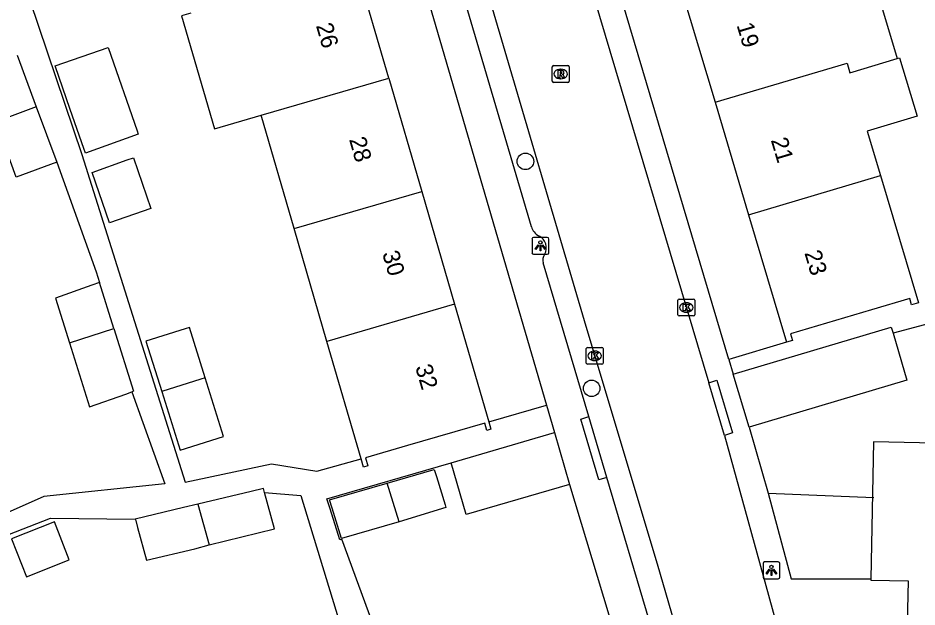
# Model space of a CAD drawing. Extents: x 162532 to 163264, y 381233 to 382042.
# Drawn here: x 162901.4 to 162954.6, y 381795 to 381829.9 of the extents above; entities that cross this region are included whole.
import ezdxf

# ---------------------------------------------------------------- set-up
doc = ezdxf.new("R2010")
doc.units = 0
for name, color, linetype in [('IMGEO_Boom', 7, 'Continuous'), ('IMGEO_Kolk', 7, 'Continuous'), ('IMGEO_Lichtpunt', 7, 'Continuous'), ('IMGEO_Muur', 7, 'Continuous'), ('IMGEO_Pand', 7, 'Continuous'), ('IMGEO_Pand_nummerreeks', 7, 'Continuous'), ('IMGEO_Rijbaan_lokaal_open', 7, 'Continuous'), ('IMGEO_Rioolput', 7, 'Continuous'), ('IMGEO_Voetpad_open', 7, 'Continuous')]:
    doc.layers.add(name, color=color, linetype=linetype)

msp = doc.modelspace()

# ---------------------------------------------------------------- linework, layer by layer
at = {"layer": 'IMGEO_Boom'}
for centre in [(162931.471, 381821.418), (162935.39, 381807.979)]:
    msp.add_circle(centre, 0.489, dxfattribs=at)
at = {"layer": 'IMGEO_Kolk'}
for p, q in [((162940.571, 381813.266), (162941.423, 381813.266)), ((162940.496, 381812.34), (162940.496, 381813.192)), ((162940.984, 381813.046), (162941.009, 381813.046)), ((162941.497, 381813.192), (162941.497, 381812.34)), ((162941.423, 381812.266), (162940.571, 381812.266)), ((162941.007, 381812.486), (162940.982, 381812.486)), ((162935.074, 381809.477), (162935.074, 381810.329)), ((162935.149, 381810.403), (162936.001, 381810.403)), ((162935.562, 381810.183), (162935.587, 381810.183)), ((162936.075, 381810.329), (162936.075, 381809.477)), ((162935.585, 381809.623), (162935.56, 381809.623)), ((162936.001, 381809.403), (162935.149, 381809.403))]:
    msp.add_line(p, q, dxfattribs=at)
for points in [[(162940.571, 381813.266), (162941.423, 381813.266)], [(162940.496, 381812.34), (162940.496, 381813.192)], [(162940.817, 381812.966), (162940.94, 381812.966), (162940.94, 381812.815), (162941.07, 381812.966), (162941.234, 381812.966), (162941.088, 381812.815), (162941.241, 381812.566), (162941.089, 381812.566), (162941.004, 381812.73), (162940.94, 381812.663), (162940.94, 381812.566), (162940.817, 381812.566), (162940.817, 381812.966)], [(162941.497, 381813.192), (162941.497, 381812.34)], [(162941.423, 381812.266), (162940.571, 381812.266)], [(162935.074, 381809.477), (162935.074, 381810.329)], [(162935.149, 381810.403), (162936.001, 381810.403)], [(162935.395, 381810.103), (162935.518, 381810.103), (162935.518, 381809.952), (162935.648, 381810.103), (162935.812, 381810.103), (162935.666, 381809.952), (162935.819, 381809.703), (162935.667, 381809.703), (162935.582, 381809.867), (162935.518, 381809.8), (162935.518, 381809.703), (162935.395, 381809.703), (162935.395, 381810.103)], [(162936.075, 381810.329), (162936.075, 381809.477)], [(162936.001, 381809.403), (162935.149, 381809.403)]]:
    msp.add_lwpolyline(points, dxfattribs=at)
for centre, start, end in [((162940.573, 381813.19), 91.552, 178.448), ((162940.573, 381813.19), 91.552, 178.448), ((162941.421, 381813.19), 1.552, 88.448), ((162941.421, 381813.19), 1.552, 88.448), ((162940.573, 381812.342), 181.552, 268.448), ((162940.573, 381812.342), 181.552, 268.448), ((162941.421, 381812.342), 271.552, 358.448), ((162941.421, 381812.342), 271.552, 358.448), ((162935.151, 381810.327), 91.552, 178.448), ((162935.151, 381810.327), 91.552, 178.448), ((162935.999, 381810.327), 1.552, 88.448), ((162935.999, 381810.327), 1.552, 88.448), ((162935.151, 381809.479), 181.552, 268.448), ((162935.151, 381809.479), 181.552, 268.448), ((162935.999, 381809.479), 271.552, 358.448), ((162935.999, 381809.479), 271.552, 358.448)]:
    msp.add_arc(centre, 0.0765, start, end, dxfattribs=at)
for centre, major_axis, ratio, start_param, end_param in [((162940.983, 381812.766), (-0.387, 0.002), 0.722429, 4.712389, 7.853982), ((162941.008, 381812.766), (-0.39, 0.002), 0.717154, 1.570796, 4.712389), ((162935.561, 381809.903), (-0.387, 0.002), 0.722429, 4.712389, 7.853982), ((162935.586, 381809.903), (-0.39, 0.002), 0.717154, 1.570796, 4.712389)]:
    msp.add_ellipse(centre, major_axis=major_axis, ratio=ratio, start_param=start_param, end_param=end_param, dxfattribs=at)
at = {"layer": 'IMGEO_Lichtpunt'}
for p, q in [((162931.861, 381816.82), (162931.861, 381816.013)), ((162931.861, 381816.82), (162931.861, 381816.013)), ((162932.763, 381816.915), (162931.955, 381816.915)), ((162932.763, 381816.915), (162931.955, 381816.915)), ((162932.857, 381816.013), (162932.857, 381816.82)), ((162932.857, 381816.013), (162932.857, 381816.82)), ((162931.955, 381815.919), (162932.763, 381815.919)), ((162931.955, 381815.919), (162932.763, 381815.919)), ((162945.534, 381797.607), (162945.534, 381796.8)), ((162945.534, 381797.607), (162945.534, 381796.8)), ((162946.436, 381797.702), (162945.628, 381797.702)), ((162946.436, 381797.702), (162945.628, 381797.702)), ((162946.53, 381796.8), (162946.53, 381797.607)), ((162946.53, 381796.8), (162946.53, 381797.607)), ((162945.628, 381796.706), (162946.436, 381796.706)), ((162945.628, 381796.706), (162946.436, 381796.706))]:
    msp.add_line(p, q, dxfattribs=at)
for points in [[(162932.235, 381816.484), (162932.274, 381816.456), (162932.086, 381816.194), (162932.048, 381816.221), (162932.235, 381816.484)], [(162932.447, 381816.456), (162932.485, 381816.483), (162932.672, 381816.221), (162932.633, 381816.193), (162932.447, 381816.456)], [(162932.337, 381816.436), (162932.384, 381816.436), (162932.384, 381816.114), (162932.337, 381816.114), (162932.337, 381816.436)], [(162945.908, 381797.271), (162945.947, 381797.243), (162945.759, 381796.981), (162945.721, 381797.008), (162945.908, 381797.271)], [(162946.01, 381797.223), (162946.057, 381797.223), (162946.057, 381796.901), (162946.01, 381796.901), (162946.01, 381797.223)], [(162946.12, 381797.243), (162946.158, 381797.27), (162946.345, 381797.008), (162946.306, 381796.98), (162946.12, 381797.243)]]:
    msp.add_lwpolyline(points, dxfattribs=at)
for centre in [(162932.36, 381816.618), (162946.033, 381797.405)]:
    msp.add_circle(centre, 0.0994, dxfattribs=at)
for centre, start, end in [((162931.955, 381816.82), 90, 180), ((162931.955, 381816.82), 90, 180), ((162932.763, 381816.82), 0, 90), ((162932.763, 381816.82), 0, 90), ((162931.955, 381816.013), 180, 270), ((162931.955, 381816.013), 180, 270), ((162932.763, 381816.013), 270, 0), ((162932.763, 381816.013), 270, 360), ((162945.628, 381797.607), 90, 180), ((162945.628, 381797.607), 90, 180), ((162946.436, 381797.607), 0, 90), ((162946.436, 381797.607), 0, 90), ((162945.628, 381796.8), 180, 270), ((162945.628, 381796.8), 180, 270), ((162946.436, 381796.8), 270, 0), ((162946.436, 381796.8), 270, 360)]:
    msp.add_arc(centre, 0.0946, start, end, dxfattribs=at)
at = {"layer": 'IMGEO_Muur'}
for points in [[(162944.706, 381805.688), (162945.842, 381801.764), (162952.1, 381801.523)], [(162934.087, 381802.294), (162936.402, 381794.569)]]:
    msp.add_lwpolyline(points, dxfattribs=at)
at = {"layer": 'IMGEO_Pand'}
for points in [[(162948.549, 381833.825), (162948.707, 381833.295), (162951.508, 381834.128), (162953.478, 381827.505)], [(162923.387, 381826.346), (162921.441, 381833.041)], [(162940.736, 381831.502), (162942.694, 381824.919)], [(162911.667, 381830.199), (162911.119, 381830.04), (162913.064, 381823.346), (162915.827, 381824.149)], [(162905.327, 381822.181), (162904.525, 381824.498), (162903.635, 381827.069), (162906.778, 381828.158), (162908.487, 381823.223), (162908.555, 381823.025), (162905.426, 381821.896), (162905.327, 381822.181)], [(162901.391, 381827.701), (162902.515, 381824.659)], [(162942.694, 381824.919), (162950.507, 381827.243), (162950.677, 381826.672), (162953.478, 381827.505)], [(162953.478, 381827.505), (162953.621, 381827.547), (162954.649, 381824.087), (162951.705, 381823.212), (162952.49, 381820.574)], [(162915.827, 381824.149), (162923.387, 381826.346)], [(162923.387, 381826.346), (162925.334, 381819.645)], [(162902.515, 381824.659), (162900.118, 381823.763)], [(162902.515, 381824.659), (162903.732, 381821.364)], [(162942.694, 381824.919), (162944.677, 381818.251)], [(162917.774, 381817.447), (162915.827, 381824.149)], [(162903.732, 381821.364), (162901.331, 381820.478), (162900.118, 381823.763)], [(162909.303, 381818.626), (162906.852, 381817.778), (162905.821, 381820.754), (162907.897, 381821.503), (162908.265, 381821.626), (162909.303, 381818.626)], [(162944.677, 381818.251), (162952.49, 381820.574)], [(162952.49, 381820.574), (162954.728, 381813.049)], [(162917.774, 381817.447), (162925.334, 381819.645)], [(162925.334, 381819.645), (162927.278, 381812.956)], [(162944.677, 381818.251), (162946.922, 381810.704)], [(162919.718, 381810.759), (162917.774, 381817.447)], [(162906.26, 381814.246), (162905.807, 381814.083), (162903.665, 381813.314), (162904.487, 381810.683)], [(162907.112, 381811.522), (162906.26, 381814.246)], [(162954.728, 381813.049), (162954.329, 381812.93), (162954.218, 381813.304), (162951.951, 381812.63), (162947.158, 381811.205), (162947.276, 381810.809), (162946.922, 381810.704)], [(162927.278, 381812.956), (162919.718, 381810.759)], [(162927.278, 381812.956), (162929.302, 381805.991)], [(162904.487, 381810.683), (162907.112, 381811.522)], [(162907.112, 381811.522), (162908.274, 381807.809), (162908.175, 381807.773)], [(162912.514, 381808.598), (162911.584, 381811.574), (162911.338, 381811.497), (162909.011, 381810.77), (162909.942, 381807.794)], [(162943.773, 381808.826), (162953.122, 381811.605), (162953.229, 381811.245)], [(162953.229, 381811.245), (162954.055, 381808.468), (162944.706, 381805.688)], [(162904.487, 381810.683), (162905.678, 381806.877), (162907.812, 381807.643), (162908.175, 381807.773)], [(162921.741, 381803.799), (162919.718, 381810.759)], [(162909.942, 381807.794), (162911.028, 381804.323), (162913.599, 381805.127), (162912.514, 381808.598)], [(162912.514, 381808.598), (162912.268, 381808.521), (162909.942, 381807.794)], [(162944.706, 381805.688), (162943.773, 381808.826)], [(162929.302, 381805.991), (162929.429, 381805.553), (162929.193, 381805.485), (162929.065, 381805.923), (162924.501, 381804.597), (162922.005, 381803.871), (162922.143, 381803.395), (162921.88, 381803.319), (162921.741, 381803.799)], [(162927.072, 381803.576), (162933.197, 381805.356)], [(162933.197, 381805.356), (162934.087, 381802.294)], [(162959.247, 381801.376), (162959.314, 381804.662), (162952.08, 381804.81), (162951.914, 381796.703)], [(162923.286, 381802.363), (162926.076, 381803.173), (162926.2, 381802.768), (162926.717, 381801.079), (162926.763, 381800.928), (162923.999, 381800.083)], [(162934.087, 381802.294), (162927.962, 381800.514), (162927.072, 381803.576)], [(162923.999, 381800.083), (162920.577, 381799.088), (162920.028, 381800.879), (162919.878, 381801.372), (162923.286, 381802.363)], [(162923.999, 381800.083), (162923.286, 381802.363)], [(162916.03, 381801.808), (162915.965, 381802.046), (162915.246, 381801.875), (162912.088, 381801.122)], [(162912.745, 381798.712), (162916.615, 381799.661), (162916.03, 381801.808)], [(162912.088, 381801.122), (162911.238, 381800.919), (162908.378, 381800.237)], [(162912.088, 381801.122), (162912.745, 381798.712)], [(162903.589, 381800.072), (162901.045, 381799.071), (162901.931, 381796.819), (162904.475, 381797.82), (162903.589, 381800.072)], [(162908.378, 381800.237), (162908.403, 381800.146), (162908.513, 381799.742), (162909.042, 381797.8), (162911.902, 381798.482), (162912.745, 381798.712)], [(162951.914, 381796.703), (162951.912, 381796.623), (162954.122, 381796.578), (162954.052, 381793.156)]]:
    msp.add_lwpolyline(points, dxfattribs=at)
at = {"layer": 'IMGEO_Rijbaan_lokaal_open'}
for points in [[(162924.919, 381866.714), (162928.526, 381854.515), (162935.521, 381831.16), (162942.322, 381808.313)], [(162919.376, 381864.437), (162923.481, 381850.642), (162929.495, 381830.491), (162935.047, 381811.667), (162939.272, 381797.593), (162940.933, 381791.879)], [(162943.251, 381805.194), (162942.322, 381808.313)], [(162943.251, 381805.194), (162946.232, 381794.364), (162947.14, 381791.276), (162946.337, 381789.764)]]:
    msp.add_lwpolyline(points, dxfattribs=at)
at = {"layer": 'IMGEO_Rioolput'}
for p, q in [((162933.136, 381827.094), (162933.988, 381827.094)), ((162933.061, 381826.168), (162933.061, 381827.02)), ((162933.549, 381826.874), (162933.574, 381826.874)), ((162934.062, 381827.02), (162934.062, 381826.168)), ((162933.988, 381826.094), (162933.136, 381826.094)), ((162933.572, 381826.314), (162933.547, 381826.314))]:
    msp.add_line(p, q, dxfattribs=at)
for points in [[(162933.136, 381827.094), (162933.988, 381827.094)], [(162933.061, 381826.168), (162933.061, 381827.02)], [(162933.65, 381826.792), (162933.398, 381826.794), (162933.398, 381826.394)], [(162933.398, 381826.394), (162933.522, 381826.394), (162933.522, 381826.556), (162933.533, 381826.556)], [(162933.576, 381826.713), (162933.522, 381826.713), (162933.522, 381826.632)], [(162933.522, 381826.632), (162933.574, 381826.632)], [(162934.062, 381827.02), (162934.062, 381826.168)], [(162933.988, 381826.094), (162933.136, 381826.094)], [(162933.58, 381826.527), (162933.651, 381826.394), (162933.791, 381826.394), (162933.726, 381826.52)]]:
    msp.add_lwpolyline(points, dxfattribs=at)
for centre, radius, start, end in [((162933.138, 381827.018), 0.0765, 91.552, 178.448), ((162933.138, 381827.018), 0.0765, 91.552, 178.448), ((162933.986, 381827.018), 0.0765, 1.552, 88.448), ((162933.986, 381827.018), 0.0765, 1.552, 88.448), ((162933.532, 381826.503), 0.0533, 26.0293, 88.6989), ((162933.558, 381826.821), 0.19, 274.7715, 282.9687), ((162933.582, 381826.617), 0.0964, 77.0061, 93.1865), ((162933.596, 381826.674), 0.0378, 276.6634, 79.6772), ((162933.649, 381826.682), 0.109, 350.3612, 89.416), ((162933.647, 381826.682), 0.112, 277.5842, 350.9817), ((162933.631, 381826.467), 0.108, 29.5134, 73.7905), ((162933.138, 381826.17), 0.0765, 181.552, 268.448), ((162933.138, 381826.17), 0.0765, 181.552, 268.448), ((162933.986, 381826.17), 0.0765, 271.552, 358.448), ((162933.986, 381826.17), 0.0765, 271.552, 358.448)]:
    msp.add_arc(centre, radius, start, end, dxfattribs=at)
for centre, major_axis, ratio, start_param, end_param in [((162933.548, 381826.594), (-0.387, 0.002), 0.722429, 4.712389, 7.853982), ((162933.573, 381826.594), (-0.39, 0.002), 0.717154, 1.570796, 4.712389)]:
    msp.add_ellipse(centre, major_axis=major_axis, ratio=ratio, start_param=start_param, end_param=end_param, dxfattribs=at)
at = {"layer": 'IMGEO_Voetpad_open'}
for points in [[(162913.026, 381874.412), (162932.72, 381806.989)], [(162893.62, 381857.017), (162899.056, 381840.02), (162905.21, 381821.822), (162911.331, 381802.421), (162916.434, 381803.505), (162919.12, 381803.079), (162921.741, 381803.799)], [(162943.516, 381809.691), (162929.389, 381857.197)], [(162931.824, 381817.55), (162920.468, 381856.125)], [(162903.732, 381821.364), (162906.062, 381814.886), (162906.26, 381814.246)], [(162935.227, 381806.305), (162932.529, 381815.403)], [(162961.594, 381813.486), (162953.229, 381811.245)], [(162946.922, 381810.704), (162943.516, 381809.691)], [(162943.516, 381809.691), (162943.773, 381808.826)], [(162942.322, 381808.313), (162942.8, 381808.456), (162943.729, 381805.337), (162943.251, 381805.194)], [(162908.175, 381807.773), (162910.132, 381802.324), (162902.97, 381801.571), (162900.609, 381800.52)], [(162929.302, 381805.991), (162932.72, 381806.989)], [(162932.72, 381806.989), (162933.197, 381805.356)], [(162936.296, 381802.699), (162935.818, 381802.556), (162934.748, 381806.162), (162935.227, 381806.305)], [(162936.296, 381802.699), (162935.227, 381806.305)], [(162944.706, 381805.688), (162945.842, 381801.764), (162947.198, 381796.703), (162951.914, 381796.703)], [(162923.628, 381790.807), (162920.602, 381799.044), (162920.486, 381799.008), (162919.923, 381800.847), (162919.725, 381801.432), (162927.072, 381803.576)], [(162938.799, 381794.261), (162936.296, 381802.699)], [(162934.087, 381802.294), (162936.402, 381794.569), (162939.195, 381785.063)], [(162916.03, 381801.808), (162918.169, 381801.627), (162920.828, 381792.963)], [(162894.343, 381796.777), (162903.355, 381800.286), (162908.378, 381800.237)]]:
    msp.add_lwpolyline(points, dxfattribs=at)
for centre, radius, start, end in [((162932.723, 381817.822), 0.939, 196.8462, 239.9809), ((162931.928, 381816.298), 0.782, 330.4056, 65.4586), ((162933.104, 381815.574), 0.6, 145.7427, 196.6128)]:
    msp.add_arc(centre, radius, start, end, dxfattribs=at)

# ---------------------------------------------------------------- texts
at = {"layer": 'IMGEO_Pand_nummerreeks'}
for s, rotation, p in [('26', 286.203, (162919.065, 381829.463)), ('19', 286.564, (162943.963, 381829.49)), ('28', 286.2035, (162921.026, 381822.719)), ('21', 286.564, (162945.989, 381822.682)), ('30', 286.2035, (162922.984, 381815.978)), ('23', 286.5641, (162947.975, 381816.004)), ('32', 286.203, (162924.94, 381809.244))]:
    msp.add_text(s, height=1, rotation=rotation, dxfattribs=at).set_placement(p)

doc.saveas('drawing.dxf')
